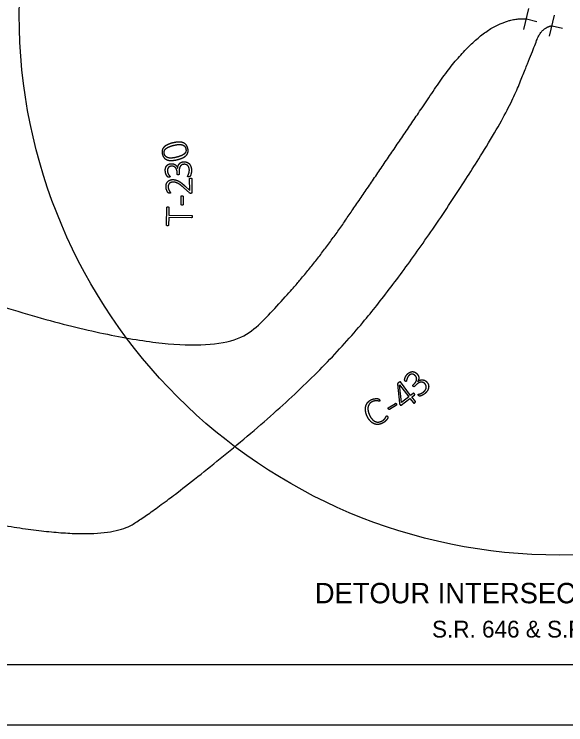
# Model space of a CAD drawing. Extents: x -740 to 1519, y 0 to 440.
# Drawn here: x 99.2 to 191, y 0 to 118.3 of the extents above; entities that cross this region are included whole.
import ezdxf

# ---------------------------------------------------------------- set-up
doc = ezdxf.new("R2010")
doc.units = 0
for name, color, linetype in [('GM_X_Minor_River', 7, 'Continuous'), ('GM_X_Section', 7, 'Continuous'), ('GM_X_Township_Text', 7, 'Continuous'), ('GM_X_Unincorporated_Location', 7, 'Continuous'), ('SH_Border', 7, 'Continuous'), ('SH_Cut_Line', 7, 'Continuous'), ('SH_Data', 7, 'Continuous')]:
    doc.layers.add(name, color=color, linetype=linetype)

msp = doc.modelspace()

# ---------------------------------------------------------------- linework, layer by layer
at = {"layer": 'GM_X_Minor_River'}
for p, q in [((184.03, 115.8), (184.87, 119.3)), ((184.45, 117.55), (186.2, 117.13)), ((188.31, 114.68), (189.15, 118.18)), ((188.73, 116.43), (190.48, 116.01))]:
    msp.add_line(p, q, dxfattribs=at)
at = {"layer": 'GM_X_Township_Text'}
for p, q in [((125.6, 96.91), (125.6, 96.91)), ((125.74, 96.51), (125.74, 96.51)), ((127.34, 93.77), (127.34, 93.77)), ((126.38, 92.69), (126.39, 92.69)), ((126.31, 91.71), (126.29, 92.08)), ((126.63, 92.15), (126.66, 91.73)), ((128.54, 91.05), (128.54, 91.05)), ((128.72, 90.94), (128.76, 88.65)), ((128.34, 88.58), (127.41, 89.43)), ((126.97, 86.64), (126.95, 88.01)), ((127.11, 88.11), (127.11, 88.11)), ((127.28, 88.02), (127.3, 86.65)), ((124.51, 83.22), (124.56, 86.15)), ((124.74, 86.25), (124.74, 86.25))]:
    msp.add_line(p, q, dxfattribs=at)
for points in [[(127.58, 89.75), (128.4, 88.99), (128.37, 90.93)], [(124.91, 86.15), (124.9, 84.88), (128.71, 84.82)], [(128.71, 84.42), (124.89, 84.48), (124.87, 83.21)]]:
    msp.add_lwpolyline(points, dxfattribs=at)
for points in [[(126.47, 97.05), (126.07, 97.02), (125.6, 96.91)], [(127.2, 96.97), (126.88, 97.07), (126.47, 97.05)], [(124.11, 96.21), (123.88, 95.98), (123.81, 95.69)], [(124.71, 96.61), (124.34, 96.44), (124.11, 96.21)], [(124.22, 95.69), (124.29, 95.82), (124.42, 95.94)], [(124.42, 95.94), (124.55, 96.05), (124.74, 96.15)], [(125.6, 96.91), (125.09, 96.78), (124.71, 96.61)], [(124.74, 96.15), (124.92, 96.25), (125.17, 96.34)], [(125.17, 96.34), (125.42, 96.43), (125.74, 96.51)], [(125.74, 96.51), (125.97, 96.56), (126.19, 96.6)], [(126.19, 96.6), (126.41, 96.64), (126.61, 96.65)], [(126.61, 96.65), (126.81, 96.65), (127, 96.62)], [(127, 96.62), (127.18, 96.59), (127.33, 96.51)], [(127.75, 96.63), (127.53, 96.87), (127.2, 96.97)], [(127.33, 96.51), (127.48, 96.43), (127.59, 96.29)], [(127.59, 96.29), (127.69, 96.15), (127.74, 95.94)], [(127.74, 95.94), (127.81, 95.68), (127.75, 95.47)], [(128.08, 95.99), (127.98, 96.4), (127.75, 96.63)], [(128.1, 95.33), (128.17, 95.62), (128.08, 95.99)], [(123.81, 95.69), (123.74, 95.4), (123.84, 95.03)], [(123.84, 95.03), (123.94, 94.62), (124.16, 94.39)], [(124.14, 95.4), (124.15, 95.56), (124.22, 95.69)], [(124.17, 95.08), (124.13, 95.25), (124.14, 95.4)], [(124.45, 94.61), (124.25, 94.76), (124.17, 95.08)], [(126.97, 94.77), (126.65, 94.63), (126.18, 94.51)], [(127.5, 95.08), (127.3, 94.91), (126.97, 94.77)], [(127.2, 94.41), (127.58, 94.58), (127.8, 94.81)], [(127.75, 95.47), (127.69, 95.25), (127.5, 95.08)], [(127.8, 94.81), (128.03, 95.04), (128.1, 95.33)], [(124.16, 94.39), (124.39, 94.15), (124.71, 94.05)], [(124.92, 94.4), (124.64, 94.45), (124.45, 94.61)], [(124.71, 94.05), (125.03, 93.95), (125.44, 93.98)], [(125.51, 94.39), (125.19, 94.35), (124.92, 94.4)], [(125.44, 93.98), (125.85, 94), (126.31, 94.11)], [(126.18, 94.51), (125.84, 94.43), (125.51, 94.39)], [(126.31, 94.11), (126.83, 94.24), (127.2, 94.41)], [(126.66, 93.43), (126.79, 93.58), (126.96, 93.67)], [(126.96, 93.67), (127.14, 93.75), (127.34, 93.77)], [(127.34, 93.77), (127.62, 93.78), (127.85, 93.71)], [(127.85, 93.71), (128.09, 93.63), (128.26, 93.47)], [(124.33, 92.24), (124.31, 92.53), (124.38, 92.75)], [(124.38, 92.75), (124.44, 92.97), (124.57, 93.12)], [(124.57, 93.12), (124.7, 93.27), (124.88, 93.35)], [(124.71, 92.56), (124.67, 92.42), (124.68, 92.23)], [(124.85, 92.81), (124.76, 92.71), (124.71, 92.56)], [(125.07, 92.96), (124.95, 92.91), (124.85, 92.81)], [(124.88, 93.35), (125.07, 93.43), (125.29, 93.44)], [(125.35, 93.03), (125.2, 93.02), (125.07, 92.96)], [(125.29, 93.44), (125.49, 93.46), (125.67, 93.41)], [(125.72, 92.98), (125.55, 93.04), (125.35, 93.03)], [(125.67, 93.41), (125.85, 93.37), (125.99, 93.27)], [(126.01, 92.79), (125.88, 92.92), (125.72, 92.98)], [(125.99, 93.27), (126.13, 93.18), (126.23, 93.03)], [(126.2, 92.49), (126.13, 92.67), (126.01, 92.79)], [(126.29, 92.08), (126.28, 92.31), (126.2, 92.49)], [(126.23, 93.03), (126.33, 92.88), (126.38, 92.69)], [(126.39, 92.69), (126.39, 92.91), (126.47, 93.1)], [(126.47, 93.1), (126.54, 93.29), (126.66, 93.43)], [(126.67, 92.63), (126.62, 92.41), (126.63, 92.15)], [(126.82, 93), (126.71, 92.85), (126.67, 92.63)], [(127.08, 93.24), (126.92, 93.15), (126.82, 93)], [(127.43, 93.34), (127.23, 93.33), (127.08, 93.24)], [(127.77, 93.3), (127.61, 93.35), (127.43, 93.34)], [(128.05, 93.14), (127.93, 93.25), (127.77, 93.3)], [(128.24, 92.85), (128.17, 93.02), (128.05, 93.14)], [(128.33, 92.44), (128.32, 92.68), (128.24, 92.85)], [(128.26, 93.47), (128.44, 93.3), (128.55, 93.04)], [(128.3, 92.02), (128.34, 92.22), (128.33, 92.44)], [(128.55, 93.04), (128.66, 92.78), (128.68, 92.43)], [(128.68, 92.43), (128.69, 92.22), (128.67, 92.04)], [(124.39, 91.88), (124.34, 92.05), (124.33, 92.24)], [(124.51, 91.58), (124.44, 91.71), (124.39, 91.88)], [(124.63, 91.37), (124.57, 91.45), (124.51, 91.58)], [(124.73, 91.25), (124.7, 91.28), (124.63, 91.37)], [(124.68, 92.23), (124.69, 92.03), (124.76, 91.87)], [(124.78, 91.21), (124.76, 91.22), (124.73, 91.25)], [(124.76, 91.87), (124.83, 91.71), (124.91, 91.58)], [(124.83, 91.19), (124.8, 91.2), (124.78, 91.21)], [(124.88, 91.18), (124.85, 91.18), (124.83, 91.19)], [(124.94, 91.18), (124.91, 91.18), (124.88, 91.18)], [(124.91, 91.58), (124.99, 91.46), (125.05, 91.39)], [(125.03, 91.19), (125, 91.18), (124.94, 91.18)], [(125.09, 91.21), (125.07, 91.2), (125.03, 91.19)], [(125.05, 91.39), (125.11, 91.31), (125.11, 91.28)], [(125.11, 91.24), (125.11, 91.22), (125.09, 91.21)], [(125.11, 91.28), (125.12, 91.26), (125.11, 91.24)], [(126.33, 91.66), (126.32, 91.68), (126.31, 91.71)], [(126.36, 91.63), (126.34, 91.64), (126.33, 91.66)], [(126.42, 91.6), (126.38, 91.61), (126.36, 91.63)], [(126.49, 91.6), (126.45, 91.6), (126.42, 91.6)], [(126.57, 91.61), (126.54, 91.6), (126.49, 91.6)], [(126.62, 91.65), (126.6, 91.63), (126.57, 91.61)], [(126.65, 91.69), (126.64, 91.67), (126.62, 91.65)], [(126.66, 91.73), (126.66, 91.71), (126.65, 91.69)], [(128.05, 91.32), (128.04, 91.35), (128.09, 91.45)], [(128.09, 91.27), (128.05, 91.29), (128.05, 91.32)], [(128.09, 91.45), (128.14, 91.54), (128.2, 91.69)], [(128.22, 91.26), (128.12, 91.25), (128.09, 91.27)], [(128.2, 91.69), (128.26, 91.83), (128.3, 92.02)], [(128.31, 91.27), (128.27, 91.26), (128.22, 91.26)], [(128.37, 91.28), (128.35, 91.27), (128.31, 91.27)], [(128.41, 91.31), (128.4, 91.29), (128.37, 91.28)], [(128.45, 91.34), (128.43, 91.32), (128.41, 91.31)], [(128.52, 91.46), (128.47, 91.37), (128.45, 91.34)], [(128.6, 91.71), (128.56, 91.56), (128.52, 91.46)], [(128.67, 92.04), (128.64, 91.85), (128.6, 91.71)], [(124.45, 89.6), (124.44, 89.89), (124.53, 90.12)], [(124.53, 90.12), (124.61, 90.34), (124.76, 90.49)], [(124.76, 90.49), (124.91, 90.64), (125.1, 90.71)], [(125.02, 90.16), (124.91, 90.06), (124.85, 89.92)], [(125.27, 90.32), (125.12, 90.26), (125.02, 90.16)], [(125.1, 90.71), (125.3, 90.79), (125.52, 90.79)], [(125.56, 90.37), (125.41, 90.37), (125.27, 90.32)], [(125.52, 90.79), (125.72, 90.8), (125.93, 90.77)], [(125.9, 90.35), (125.72, 90.38), (125.56, 90.37)], [(126.3, 90.22), (126.08, 90.32), (125.9, 90.35)], [(125.93, 90.77), (126.13, 90.73), (126.37, 90.63)], [(126.79, 89.94), (126.51, 90.13), (126.3, 90.22)], [(126.37, 90.63), (126.61, 90.52), (126.9, 90.31)], [(127.41, 89.43), (127.06, 89.75), (126.79, 89.94)], [(126.9, 90.31), (127.19, 90.1), (127.58, 89.75)], [(128.37, 90.93), (128.36, 90.96), (128.38, 90.98)], [(128.38, 90.98), (128.39, 91), (128.41, 91.02)], [(128.41, 91.02), (128.43, 91.04), (128.46, 91.05)], [(128.46, 91.05), (128.5, 91.05), (128.54, 91.05)], [(128.54, 91.05), (128.58, 91.06), (128.61, 91.05)], [(128.61, 91.05), (128.64, 91.04), (128.67, 91.03)], [(128.67, 91.03), (128.69, 91.01), (128.71, 90.99)], [(128.71, 90.99), (128.72, 90.97), (128.72, 90.94)], [(124.49, 89.25), (124.45, 89.42), (124.45, 89.6)], [(124.6, 88.95), (124.54, 89.08), (124.49, 89.25)], [(124.72, 88.72), (124.66, 88.81), (124.6, 88.95)], [(124.85, 89.92), (124.79, 89.77), (124.8, 89.58)], [(124.8, 89.58), (124.8, 89.37), (124.86, 89.21)], [(124.86, 89.21), (124.92, 89.05), (124.99, 88.93)], [(124.99, 88.93), (125.07, 88.81), (125.13, 88.73)], [(124.81, 88.59), (124.77, 88.63), (124.72, 88.72)], [(124.86, 88.55), (124.84, 88.56), (124.81, 88.59)], [(124.9, 88.53), (124.88, 88.54), (124.86, 88.55)], [(124.95, 88.52), (124.92, 88.52), (124.9, 88.53)], [(125.02, 88.52), (124.98, 88.52), (124.95, 88.52)], [(125.09, 88.52), (125.06, 88.52), (125.02, 88.52)], [(125.15, 88.54), (125.12, 88.53), (125.09, 88.52)], [(125.13, 88.73), (125.18, 88.65), (125.19, 88.61)], [(125.18, 88.57), (125.17, 88.55), (125.15, 88.54)], [(125.19, 88.61), (125.19, 88.59), (125.18, 88.57)], [(126.95, 88.01), (126.95, 88.03), (126.96, 88.05)], [(126.96, 88.05), (126.96, 88.07), (126.98, 88.08)], [(126.98, 88.08), (127, 88.1), (127.03, 88.1)], [(127.03, 88.1), (127.07, 88.11), (127.11, 88.11)], [(127.11, 88.11), (127.21, 88.11), (127.24, 88.09)], [(127.24, 88.09), (127.28, 88.06), (127.28, 88.02)], [(128.39, 88.54), (128.37, 88.56), (128.34, 88.58)], [(128.45, 88.52), (128.42, 88.53), (128.39, 88.54)], [(128.51, 88.5), (128.47, 88.51), (128.45, 88.52)], [(128.58, 88.5), (128.54, 88.5), (128.51, 88.5)], [(128.67, 88.51), (128.63, 88.5), (128.58, 88.5)], [(128.72, 88.54), (128.7, 88.52), (128.67, 88.51)], [(128.75, 88.59), (128.74, 88.56), (128.72, 88.54)], [(128.76, 88.65), (128.76, 88.62), (128.75, 88.59)], [(127.01, 86.57), (126.97, 86.6), (126.97, 86.64)], [(127.14, 86.54), (127.04, 86.54), (127.01, 86.57)], [(127.26, 86.57), (127.23, 86.55), (127.14, 86.54)], [(127.3, 86.65), (127.3, 86.6), (127.26, 86.57)], [(124.56, 86.15), (124.56, 86.17), (124.57, 86.19)], [(124.57, 86.19), (124.58, 86.21), (124.61, 86.23)], [(124.61, 86.23), (124.63, 86.24), (124.66, 86.24)], [(124.66, 86.24), (124.7, 86.25), (124.74, 86.25)], [(124.74, 86.25), (124.79, 86.25), (124.82, 86.24)], [(124.82, 86.24), (124.85, 86.23), (124.87, 86.22)], [(124.87, 86.22), (124.89, 86.21), (124.9, 86.19)], [(124.9, 86.19), (124.91, 86.17), (124.91, 86.15)], [(128.71, 84.82), (128.73, 84.82), (128.75, 84.81)], [(128.74, 84.43), (128.73, 84.42), (128.71, 84.42)], [(128.77, 84.46), (128.76, 84.44), (128.74, 84.43)], [(128.75, 84.81), (128.77, 84.8), (128.78, 84.78)], [(128.79, 84.52), (128.78, 84.49), (128.77, 84.46)], [(128.78, 84.78), (128.79, 84.75), (128.79, 84.71)], [(128.79, 84.71), (128.8, 84.68), (128.8, 84.62)], [(128.8, 84.62), (128.8, 84.56), (128.79, 84.52)], [(124.52, 83.17), (124.51, 83.19), (124.51, 83.22)], [(124.56, 83.14), (124.54, 83.15), (124.52, 83.17)], [(124.62, 83.12), (124.58, 83.13), (124.56, 83.14)], [(124.7, 83.11), (124.65, 83.11), (124.62, 83.12)], [(124.77, 83.12), (124.74, 83.11), (124.7, 83.11)], [(124.82, 83.14), (124.8, 83.12), (124.77, 83.12)], [(124.86, 83.17), (124.85, 83.15), (124.82, 83.14)], [(124.87, 83.21), (124.87, 83.19), (124.86, 83.17)]]:
    msp.add_open_spline(points, degree=2, dxfattribs=at)
at = {"layer": 'GM_X_Unincorporated_Location'}
for p, q in [((165.57, 56.57), (165.83, 56.84)), ((166.35, 57.17), (166.35, 57.17)), ((167.79, 57.16), (167.79, 57.16)), ((162.98, 56.71), (163.32, 53.55)), ((166.11, 56.63), (165.81, 56.33)), ((165.81, 55.12), (165.81, 55.12)), ((161.46, 52.81), (162.63, 53.52)), ((162.8, 53.43), (162.8, 53.43)), ((162.8, 53.24), (161.63, 52.53)), ((161.34, 51.31), (161.34, 51.31))]:
    msp.add_line(p, q, dxfattribs=at)
for points in [[(165.61, 55.18), (165.18, 54.86), (163.49, 57.09)], [(165.96, 53.82), (165.38, 54.59), (165.81, 54.91)], [(163.62, 53.25), (165.07, 54.35), (165.65, 53.59)]]:
    msp.add_lwpolyline(points, dxfattribs=at)
msp.add_lwpolyline([(163.33, 56.64), (164.87, 54.62), (163.65, 53.69), (163.33, 56.64)], close=True, dxfattribs=at)
for points in [[(164.28, 57.85), (164.33, 57.98), (164.43, 58.13)], [(164.43, 58.13), (164.52, 58.28), (164.66, 58.42)], [(164.66, 58.42), (164.86, 58.62), (165.07, 58.72)], [(164.88, 58.14), (164.73, 58), (164.66, 57.84)], [(165.15, 58.34), (165.01, 58.28), (164.88, 58.14)], [(165.07, 58.72), (165.28, 58.81), (165.48, 58.82)], [(165.43, 58.4), (165.29, 58.4), (165.15, 58.34)], [(165.69, 58.33), (165.56, 58.39), (165.43, 58.4)], [(165.48, 58.82), (165.67, 58.82), (165.85, 58.73)], [(165.92, 58.17), (165.82, 58.27), (165.69, 58.33)], [(165.85, 58.73), (166.04, 58.65), (166.19, 58.49)], [(166.13, 57.86), (166.06, 58.03), (165.92, 58.17)], [(166.19, 58.49), (166.34, 58.35), (166.42, 58.18)], [(166.42, 58.18), (166.51, 58.02), (166.53, 57.85)], [(163.02, 56.83), (163, 56.8), (162.99, 56.77)], [(163.08, 56.9), (163.05, 56.86), (163.02, 56.83)], [(163.18, 56.98), (163.12, 56.93), (163.08, 56.9)], [(163.29, 57.05), (163.24, 57.02), (163.18, 56.98)], [(163.38, 57.1), (163.34, 57.08), (163.29, 57.05)], [(163.45, 57.11), (163.42, 57.11), (163.38, 57.1)], [(163.49, 57.09), (163.47, 57.11), (163.45, 57.11)], [(164.18, 57.46), (164.18, 57.5), (164.2, 57.61)], [(164.18, 57.39), (164.18, 57.42), (164.18, 57.46)], [(164.2, 57.35), (164.19, 57.37), (164.18, 57.39)], [(164.2, 57.61), (164.22, 57.72), (164.28, 57.85)], [(164.22, 57.3), (164.21, 57.32), (164.2, 57.35)], [(164.27, 57.25), (164.24, 57.28), (164.22, 57.3)], [(164.33, 57.19), (164.31, 57.21), (164.27, 57.25)], [(164.38, 57.17), (164.36, 57.17), (164.33, 57.19)], [(164.42, 57.17), (164.41, 57.16), (164.38, 57.17)], [(164.45, 57.19), (164.44, 57.18), (164.42, 57.17)], [(164.49, 57.31), (164.48, 57.21), (164.45, 57.19)], [(164.55, 57.55), (164.51, 57.41), (164.49, 57.31)], [(164.66, 57.84), (164.59, 57.69), (164.55, 57.55)], [(165.83, 56.84), (165.99, 57), (166.08, 57.17)], [(166.08, 57.17), (166.17, 57.35), (166.18, 57.52)], [(166.49, 56.92), (166.3, 56.81), (166.11, 56.63)], [(166.18, 57.52), (166.19, 57.7), (166.13, 57.86)], [(166.51, 57.51), (166.46, 57.34), (166.35, 57.17)], [(166.35, 57.17), (166.52, 57.31), (166.71, 57.38)], [(166.87, 57.05), (166.69, 57.03), (166.49, 56.92)], [(166.53, 57.85), (166.55, 57.68), (166.51, 57.51)], [(166.71, 57.38), (166.9, 57.45), (167.09, 57.45)], [(167.22, 57.01), (167.06, 57.07), (166.87, 57.05)], [(167.09, 57.45), (167.29, 57.45), (167.47, 57.38)], [(167.53, 56.82), (167.39, 56.96), (167.22, 57.01)], [(167.47, 57.38), (167.65, 57.31), (167.79, 57.16)], [(167.73, 56.54), (167.66, 56.69), (167.53, 56.82)], [(167.79, 57.16), (167.99, 56.97), (168.09, 56.74)], [(162.99, 56.77), (162.98, 56.74), (162.98, 56.71)], [(165.54, 56.53), (165.55, 56.55), (165.57, 56.57)], [(165.54, 56.48), (165.53, 56.51), (165.54, 56.53)], [(165.56, 56.43), (165.54, 56.46), (165.54, 56.48)], [(165.6, 56.37), (165.57, 56.4), (165.56, 56.43)], [(165.67, 56.32), (165.64, 56.33), (165.6, 56.37)], [(165.73, 56.3), (165.7, 56.3), (165.67, 56.32)], [(165.78, 56.31), (165.75, 56.3), (165.73, 56.3)], [(165.81, 56.33), (165.8, 56.32), (165.78, 56.31)], [(167.45, 55.55), (167.62, 55.71), (167.7, 55.88)], [(168.04, 55.78), (167.92, 55.52), (167.68, 55.28)], [(167.7, 55.88), (167.78, 56.05), (167.79, 56.22)], [(167.79, 56.22), (167.79, 56.38), (167.73, 56.54)], [(168.18, 56.27), (168.17, 56.03), (168.04, 55.78)], [(168.09, 56.74), (168.18, 56.52), (168.18, 56.27)], [(165.7, 55.2), (165.65, 55.22), (165.61, 55.18)], [(165.81, 55.12), (165.76, 55.19), (165.7, 55.2)], [(165.86, 55), (165.85, 55.06), (165.81, 55.12)], [(165.81, 54.91), (165.86, 54.95), (165.86, 55)], [(166.41, 54.95), (166.4, 54.99), (166.42, 55.02)], [(166.49, 54.84), (166.42, 54.91), (166.41, 54.95)], [(166.42, 55.02), (166.44, 55.04), (166.55, 55.06)], [(166.56, 54.78), (166.53, 54.81), (166.49, 54.84)], [(166.55, 55.06), (166.65, 55.09), (166.8, 55.14)], [(166.61, 54.75), (166.59, 54.76), (166.56, 54.78)], [(166.65, 54.73), (166.63, 54.74), (166.61, 54.75)], [(166.71, 54.73), (166.68, 54.73), (166.65, 54.73)], [(166.84, 54.76), (166.74, 54.73), (166.71, 54.73)], [(166.8, 55.14), (166.94, 55.2), (167.12, 55.29)], [(167.08, 54.86), (166.94, 54.79), (166.84, 54.76)], [(167.37, 55.03), (167.22, 54.92), (167.08, 54.86)], [(167.12, 55.29), (167.29, 55.39), (167.45, 55.55)], [(167.68, 55.28), (167.53, 55.13), (167.37, 55.03)], [(157.71, 53.04), (157.8, 53.4), (158.03, 53.68)], [(158.03, 53.68), (158.27, 53.96), (158.63, 54.14)], [(158.33, 53.46), (158.15, 53.24), (158.09, 52.95)], [(158.77, 53.8), (158.5, 53.67), (158.33, 53.46)], [(158.63, 54.14), (158.81, 54.22), (158.98, 54.26)], [(159.22, 53.94), (159.02, 53.91), (158.77, 53.8)], [(158.98, 54.26), (159.16, 54.3), (159.32, 54.32)], [(159.59, 53.95), (159.43, 53.96), (159.22, 53.94)], [(159.32, 54.32), (159.48, 54.33), (159.62, 54.32)], [(159.85, 53.91), (159.75, 53.93), (159.59, 53.95)], [(159.62, 54.32), (159.76, 54.31), (159.82, 54.28)], [(159.82, 54.28), (159.88, 54.26), (159.89, 54.25)], [(160, 53.9), (159.96, 53.88), (159.85, 53.91)], [(159.89, 54.25), (159.91, 54.24), (159.93, 54.22)], [(159.93, 54.22), (159.95, 54.2), (159.96, 54.17)], [(159.96, 54.17), (159.98, 54.15), (160, 54.11)], [(160, 54.11), (160.01, 54.07), (160.03, 54.03)], [(160.03, 53.93), (160.02, 53.91), (160, 53.9)], [(160.03, 54.03), (160.04, 54), (160.04, 53.97)], [(160.04, 53.97), (160.04, 53.95), (160.03, 53.93)], [(162.63, 53.52), (162.65, 53.53), (162.67, 53.54)], [(162.67, 53.54), (162.69, 53.54), (162.71, 53.53)], [(162.71, 53.53), (162.73, 53.52), (162.75, 53.49)], [(162.75, 53.49), (162.77, 53.47), (162.8, 53.43)], [(162.8, 53.43), (162.85, 53.35), (162.84, 53.31)], [(162.84, 53.31), (162.84, 53.27), (162.8, 53.24)], [(163.32, 53.55), (163.32, 53.51), (163.33, 53.48)], [(163.33, 53.48), (163.33, 53.45), (163.34, 53.42)], [(163.34, 53.42), (163.35, 53.4), (163.37, 53.37)], [(163.37, 53.37), (163.39, 53.34), (163.41, 53.31)], [(163.41, 53.31), (163.44, 53.27), (163.47, 53.24)], [(165.65, 53.59), (165.66, 53.57), (165.68, 53.56)], [(165.68, 53.56), (165.7, 53.55), (165.72, 53.56)], [(165.72, 53.56), (165.74, 53.57), (165.78, 53.58)], [(165.78, 53.58), (165.81, 53.6), (165.86, 53.63)], [(165.86, 53.63), (165.9, 53.67), (165.93, 53.7)], [(165.93, 53.7), (165.96, 53.73), (165.97, 53.75)], [(165.98, 53.79), (165.98, 53.81), (165.96, 53.82)], [(165.97, 53.75), (165.98, 53.77), (165.98, 53.79)], [(157.67, 52.25), (157.62, 52.68), (157.71, 53.04)], [(157.95, 51.36), (157.73, 51.82), (157.67, 52.25)], [(158.09, 52.95), (158.03, 52.67), (158.09, 52.32)], [(158.09, 52.32), (158.14, 51.97), (158.33, 51.57)], [(161.41, 52.74), (161.42, 52.78), (161.46, 52.81)], [(161.46, 52.62), (161.41, 52.69), (161.41, 52.74)], [(161.55, 52.52), (161.5, 52.54), (161.46, 52.62)], [(161.63, 52.53), (161.59, 52.5), (161.55, 52.52)], [(163.47, 53.24), (163.5, 53.22), (163.52, 53.22)], [(163.52, 53.22), (163.55, 53.21), (163.57, 53.22)], [(163.57, 53.22), (163.59, 53.23), (163.62, 53.25)], [(158.45, 50.6), (158.17, 50.9), (157.95, 51.36)], [(158.33, 51.57), (158.51, 51.18), (158.74, 50.93)], [(158.74, 50.93), (158.96, 50.67), (159.21, 50.54)], [(160.71, 50.82), (160.86, 50.96), (160.96, 51.1)], [(160.96, 51.1), (161.05, 51.23), (161.1, 51.33)], [(161.1, 51.33), (161.15, 51.43), (161.2, 51.45)], [(161.29, 50.94), (161.22, 50.83), (161.11, 50.7)], [(161.2, 51.45), (161.22, 51.46), (161.23, 51.46)], [(161.23, 51.46), (161.25, 51.45), (161.26, 51.44)], [(161.26, 51.44), (161.28, 51.42), (161.3, 51.39)], [(161.37, 51.09), (161.35, 51.05), (161.29, 50.94)], [(161.3, 51.39), (161.32, 51.36), (161.34, 51.31)], [(161.34, 51.31), (161.36, 51.28), (161.37, 51.25)], [(161.37, 51.25), (161.38, 51.23), (161.38, 51.2)], [(161.38, 51.16), (161.38, 51.13), (161.37, 51.09)], [(161.38, 51.2), (161.38, 51.18), (161.38, 51.16)], [(159.05, 50.15), (158.73, 50.29), (158.45, 50.6)], [(159.72, 50.01), (159.37, 50), (159.05, 50.15)], [(159.21, 50.54), (159.47, 50.41), (159.75, 50.41)], [(160.44, 50.2), (160.08, 50.03), (159.72, 50.01)], [(159.75, 50.41), (160.03, 50.42), (160.32, 50.56)], [(160.32, 50.56), (160.56, 50.67), (160.71, 50.82)], [(160.83, 50.44), (160.66, 50.31), (160.44, 50.2)], [(161.11, 50.7), (160.99, 50.57), (160.83, 50.44)]]:
    msp.add_open_spline(points, degree=2, dxfattribs=at)
at = {"layer": 'SH_Border'}
msp.add_lwpolyline([(30, 430), (670, 430), (670, 10), (30, 10)], close=True, dxfattribs=at)
at = {"layer": 'SH_Cut_Line'}
msp.add_lwpolyline([(0, 0), (680, 0), (680, 440), (0, 440)], close=True, dxfattribs=at)
at = {"layer": 'SH_Data'}
msp.add_circle((190, 118.25), 90, dxfattribs=at)
for points in [[(90.79, 71.66), (131.41, 58.3), (147.57, 74.14), (161.29, 94.19), (177.49, 118.16), (184.45, 117.55)], [(96.17, 33.44), (113.8, 30.27), (123.98, 36.5), (147.54, 55.93), (162.63, 73.1), (180.67, 100.31), (185.41, 111.96), (186.96, 116.11), (188.73, 116.43)]]:
    msp.add_open_spline(points, degree=2, dxfattribs=at)

# ---------------------------------------------------------------- texts
at = {"layer": 'GM_X_Section'}
for s, height, p in [('DETOUR INTERSECTION DETAIL 3', 3.4, (149.23, 20.23)), ('S.R. 646 & S.R. 151', 2.8, (168.74, 14.53))]:
    msp.add_text(s, height=height, dxfattribs=at).set_placement(p)

doc.saveas('drawing.dxf')
